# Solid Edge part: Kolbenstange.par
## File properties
Username: bmolnar
Dokumentum tartalom típus: 0
Author: bmolnar
Last saved by: bmolnar
Revision: 92
Sűrűség: 0,000 kg/m^3
Pontosság: 0,990
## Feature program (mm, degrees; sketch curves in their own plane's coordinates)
base feature "unnamed BaseFeature 1"
sketch for "unnamed Protrusion 1" plane through (30, 0, 0) normal (1, 0, 0) x-axis (0, -1, 0)
  circle centre (0, 0) radius 25
extrude "unnamed Protrusion 1" add finite 8.5 along +normal
sketch for "Kihúzás_2" plane through (30, 0, 0) normal (1, 0, 0) x-axis (0, -1, 0)
  circle centre (0, 0) radius 25
extrude "Kihúzás_2" add finite 7.5 along -normal
sketch for "Furat_2" plane through (-125, 0, 0) normal (-1, 0, 0) x-axis (0, 0, -1)
  hole centre (0, 0) bore radius 4.188
hole "Furat_2" nominal diameter 10 finite  ThreadDepth = 17 mm
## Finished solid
Body 1: solid body, 14 faces, 20 edges, 8 vertices.
  Faces by surface: plane 8, cylinder 4, cone 1, torus 1
  Edges by curve: circle 10, line 6, ellipse 2, intersection 2
Bounding box of the edges (mm; curved faces can reach further): 163.500 x 50.000 x 50.000, from (-125, -25, -25) to (38.5, 25, 25).
Cylindrical faces by radius (mm): R4.188 x2, R8 x1, R25 x1
Conical faces (half-angle, radius in mm at the cone's reference point): 45 deg R4.538 x1
Toroidal faces (ring radius, tube radius in mm): R6.3 r1.7 x1
Planar faces by outward normal: +x 1, +z 1, -x 3, -z 1, oblique 2
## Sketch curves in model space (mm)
circle centre (30, 0, 0) radius 25
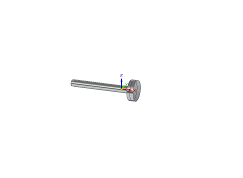
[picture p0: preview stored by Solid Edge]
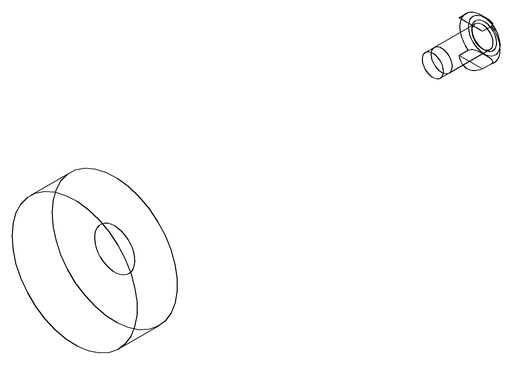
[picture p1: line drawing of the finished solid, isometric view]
